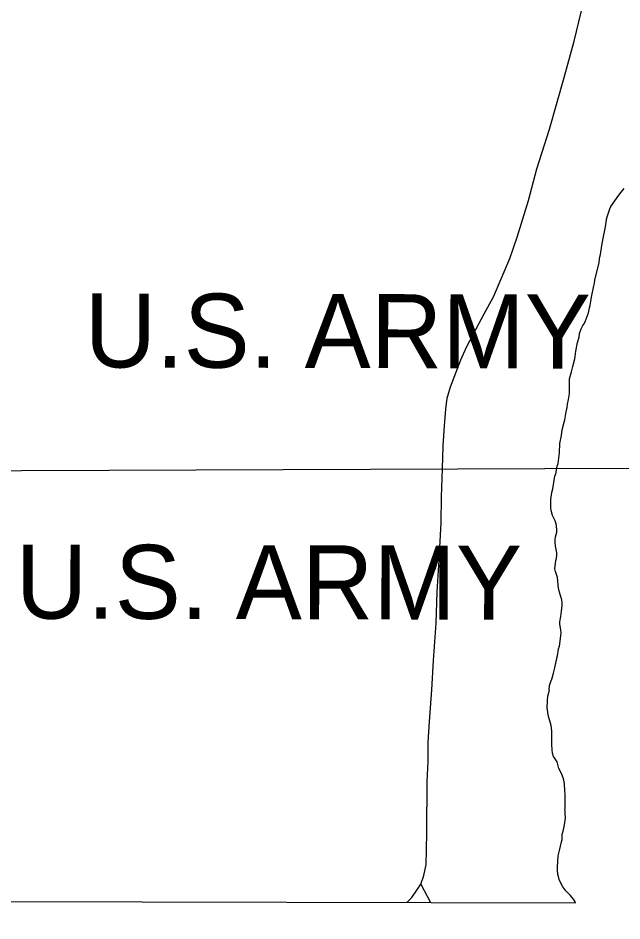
# Model space of a CAD drawing. Extents: x 3172297 to 3210190, y 958463 to 983887.
# Drawn here: x 3187541 to 3188356, y 963866 to 965086 of the extents above; entities that cross this region are included whole.
import ezdxf

# ---------------------------------------------------------------- set-up
doc = ezdxf.new("R2010")
doc.units = 0
for name, color, linetype in [('V-ROAD-CNTR', 7, 'Continuous'), ('V-SITE-VEGE', 7, 'Continuous'), ('V-TOPO-BNDY', 7, 'Continuous'), ('V-TOPO-GNAM-IDEN', 7, 'Continuous'), ('V-TOPO-SHOR', 7, 'Continuous')]:
    doc.layers.add(name, color=color, linetype=linetype)

msp = doc.modelspace()

# ---------------------------------------------------------------- linework, layer by layer
at = {"layer": 'V-ROAD-CNTR'}
for points in [[(3188084.8, 963915.8), (3188089, 963927.4), (3188092.1, 963942.4), (3188092.6, 963962), (3188093.1, 963985.5), (3188093.2, 964054.6), (3188094.6, 964081.6), (3188094.7, 964107.7), (3188096.4, 964135.6), (3188099.8, 964178.2), (3188102.1, 964218.1), (3188105.6, 964268.6), (3188106.8, 964310.6), (3188109.6, 964354), (3188112.2, 964404.2), (3188112.8, 964439.3), (3188114.2, 964477.2), (3188115, 964507.9), (3188116.8, 964535.1), (3188118.6, 964557.8), (3188120.5, 964572.4), (3188124.7, 964587.8), (3188138.9, 964624.3), (3188146.6, 964641.5), (3188155.4, 964658.7), (3188170.5, 964686.3), (3188182.8, 964709.3), (3188193.4, 964733.7), (3188205, 964761.3), (3188215.1, 964790.2), (3188230.4, 964839.8), (3188241.6, 964882.2), (3188258.6, 964936.2), (3188268.1, 964969.5), (3188278.3, 965005.8), (3188291.9, 965054.7), (3188307.7, 965120.7)], [(3188065.9, 963891), (3188072.8, 963898), (3188079.6, 963907.6), (3188084.8, 963915.8)], [(3188084.8, 963915.8), (3188097.9, 963890.9)]]:
    msp.add_lwpolyline(points, dxfattribs=at)
at = {"layer": 'V-SITE-VEGE'}
for p, q in [((3188355.4, 964850.9), (3188359.6, 964855.8)), ((3188341.6, 964831.7), (3188352.1, 964846.7)), ((3188352.1, 964846.7), (3188355.4, 964850.9)), ((3188339.9, 964828.2), (3188341.6, 964831.7)), ((3188336.3, 964817.6), (3188339.9, 964828.2)), ((3188333.9, 964801.7), (3188334.6, 964806.9)), ((3188334.6, 964806.9), (3188335, 964810.8)), ((3188335, 964810.8), (3188336.3, 964817.6)), ((3188331, 964788.6), (3188333.9, 964801.7)), ((3188329.2, 964778.7), (3188331, 964788.6)), ((3188327.6, 964766.5), (3188329.2, 964778.7)), ((3188325.6, 964755.6), (3188326.1, 964760.2)), ((3188326.1, 964760.2), (3188326.6, 964763.4)), ((3188326.6, 964763.4), (3188327.6, 964766.5)), ((3188319.7, 964731.8), (3188325.6, 964755.6)), ((3188315.2, 964709.2), (3188318.3, 964724.2)), ((3188318.3, 964724.2), (3188319.2, 964727.9)), ((3188319.2, 964727.9), (3188319.7, 964731.8)), ((3188313.5, 964697.9), (3188315.2, 964709.2)), ((3188312.8, 964694.6), (3188313.5, 964697.9)), ((3188310.1, 964684.2), (3188311.2, 964687.7)), ((3188311.2, 964687.7), (3188312.8, 964694.6)), ((3188303.5, 964670.7), (3188305.3, 964673.1)), ((3188305.3, 964673.1), (3188307.1, 964677.2)), ((3188307.1, 964677.2), (3188308.4, 964680.7)), ((3188308.4, 964680.7), (3188310.1, 964684.2)), ((3188298.7, 964655.1), (3188299.1, 964660.1)), ((3188299.1, 964660.1), (3188301.3, 964666.4)), ((3188301.3, 964666.4), (3188303.5, 964670.7)), ((3188296.5, 964647.5), (3188298.7, 964655.1)), ((3188293.2, 964628.7), (3188294.2, 964635.9)), ((3188294.2, 964635.9), (3188296.5, 964647.5)), ((3188290.1, 964615.5), (3188292.7, 964625.5)), ((3188292.7, 964625.5), (3188293.2, 964628.7)), ((3188288.5, 964608), (3188290.1, 964615.5)), ((3188285.8, 964598.7), (3188286.5, 964601.8)), ((3188286.5, 964601.8), (3188288.5, 964608)), ((3188285.4, 964591.1), (3188285.8, 964598.7)), ((3188285.6, 964582.6), (3188285.4, 964591.1)), ((3188284.4, 964570.6), (3188285.5, 964578.7)), ((3188285.5, 964578.7), (3188285.6, 964582.6)), ((3188282.4, 964559.7), (3188283.1, 964564.3)), ((3188283.1, 964564.3), (3188284.4, 964570.6)), ((3188279.1, 964543.4), (3188281.1, 964553.9)), ((3188281.1, 964553.9), (3188282.4, 964559.7)), ((3188275.8, 964529.7), (3188278.2, 964540.1)), ((3188278.2, 964540.1), (3188279.1, 964543.4)), ((3188274.6, 964522.1), (3188275.8, 964529.7)), ((3188272.4, 964511.2), (3188274.6, 964522.1)), ((3188272, 964498.8), (3188272.4, 964511.2)), ((3188270.2, 964484.2), (3188272, 964498.8)), ((3188267, 964470.3), (3188269.1, 964480.7)), ((3188269.1, 964480.7), (3188270.2, 964484.2)), ((3188263.1, 964449.8), (3188266, 964467)), ((3188266, 964467), (3188267, 964470.3)), ((3188260.4, 964435.5), (3188261.9, 964445.2)), ((3188261.9, 964445.2), (3188263.1, 964449.8)), ((3188260.2, 964428.3), (3188260.4, 964435.5)), ((3188260.4, 964424.4), (3188260.2, 964428.3)), ((3188261, 964420.7), (3188260.4, 964424.4)), ((3188262.7, 964414.1), (3188261, 964420.7)), ((3188266.1, 964406.9), (3188262.7, 964414.1)), ((3188267.5, 964402.8), (3188266.1, 964406.9)), ((3188268.1, 964399.7), (3188267.5, 964402.8)), ((3188268.5, 964394.7), (3188268.1, 964399.7)), ((3188268.3, 964391.6), (3188268.5, 964394.7)), ((3188266.3, 964381.6), (3188266.5, 964385.3)), ((3188266.3, 964377.9), (3188266.3, 964381.6)), ((3188266.5, 964385.3), (3188267.6, 964388.4)), ((3188267.6, 964388.4), (3188268.3, 964391.6)), ((3188266.9, 964372.7), (3188266.3, 964377.9)), ((3188268.6, 964363.6), (3188266.9, 964372.7)), ((3188267.1, 964353.1), (3188267.9, 964356.1)), ((3188267.9, 964356.1), (3188268.6, 964360.3)), ((3188268.6, 964360.3), (3188268.6, 964363.6)), ((3188265.9, 964341.8), (3188266.6, 964349.4)), ((3188266.6, 964349.4), (3188267.1, 964353.1)), ((3188266.6, 964338.3), (3188265.9, 964341.8)), ((3188269.4, 964330.2), (3188266.6, 964338.3)), ((3188270.8, 964315.4), (3188269.4, 964330.2)), ((3188273.2, 964307.3), (3188270.8, 964315.4)), ((3188275.1, 964300.2), (3188273.2, 964307.3)), ((3188275.8, 964295.6), (3188275.1, 964300.2)), ((3188275.9, 964292.5), (3188275.8, 964295.6)), ((3188273.7, 964277.7), (3188275, 964284.7)), ((3188275, 964284.7), (3188275.9, 964292.5)), ((3188272.6, 964270.3), (3188273.7, 964277.7)), ((3188272.6, 964267.1), (3188272.6, 964270.3)), ((3188274.1, 964259.7), (3188272.6, 964267.1)), ((3188274.3, 964254.9), (3188274.1, 964259.7)), ((3188273.2, 964244.2), (3188274.1, 964251.8)), ((3188274.1, 964251.8), (3188274.3, 964254.9)), ((3188270.1, 964230.7), (3188270.7, 964234)), ((3188270.7, 964234), (3188272, 964237.6)), ((3188272, 964237.6), (3188273.2, 964244.2)), ((3188265.4, 964206.3), (3188269.8, 964227.2)), ((3188269.8, 964227.2), (3188270.1, 964230.7)), ((3188261.8, 964192.8), (3188264.1, 964200.9)), ((3188264.1, 964200.9), (3188265.4, 964206.3)), ((3188258.3, 964178.2), (3188258.6, 964184.3)), ((3188258.6, 964184.3), (3188260.3, 964189.6)), ((3188260.3, 964189.6), (3188261.8, 964192.8)), ((3188256.3, 964169.8), (3188258.5, 964178)), ((3188258.5, 964178), (3188258.3, 964178.2)), ((3188255.6, 964153.9), (3188255.7, 964163.4)), ((3188255.7, 964163.4), (3188256.3, 964169.8)), ((3188257.3, 964142.5), (3188255.6, 964153.9)), ((3188259, 964136.7), (3188257.3, 964142.5)), ((3188260.7, 964130.1), (3188259, 964136.7)), ((3188261.4, 964126), (3188260.7, 964130.1)), ((3188261.6, 964122.9), (3188261.4, 964126)), ((3188261.6, 964113.5), (3188261.6, 964122.9)), ((3188261.8, 964109.4), (3188261.6, 964113.5)), ((3188261.7, 964104.6), (3188261.8, 964109.4)), ((3188262.1, 964097.2), (3188261.7, 964104.6)), ((3188262.6, 964092.9), (3188262.1, 964097.2)), ((3188264.1, 964088.5), (3188262.6, 964092.9)), ((3188266.2, 964085), (3188264.1, 964088.5)), ((3188269, 964080.9), (3188266.2, 964085)), ((3188271.2, 964072.1), (3188269, 964080.9)), ((3188274.7, 964065.4), (3188271.2, 964072.1)), ((3188277.2, 964059.5), (3188274.7, 964065.4)), ((3188278.1, 964056.4), (3188277.2, 964059.5)), ((3188279, 964051.2), (3188278.1, 964056.4)), ((3188279.3, 964041.8), (3188279, 964051.2)), ((3188279.8, 964037.5), (3188279.3, 964041.8)), ((3188279.6, 964035.7), (3188279.8, 964037.5)), ((3188279.9, 964022.4), (3188279.6, 964035.7)), ((3188279.5, 964016.8), (3188279.7, 964017)), ((3188279.9, 964013.8), (3188279.5, 964016.8)), ((3188279.7, 964017), (3188279.9, 964022.4)), ((3188279.9, 964010.2), (3188279.9, 964013.8)), ((3188277.8, 963991.7), (3188279.9, 964001.5)), ((3188280.3, 964006.5), (3188279.9, 964010.2)), ((3188279.9, 964001.5), (3188280.3, 964006.5)), ((3188277.2, 963987.6), (3188277.8, 963991.7)), ((3188275.6, 963976.3), (3188275.9, 963980.2)), ((3188275.9, 963983.5), (3188277.2, 963987.6)), ((3188275.9, 963980.2), (3188275.9, 963983.5)), ((3188272.5, 963963.2), (3188273.4, 963967.2)), ((3188273.4, 963967.2), (3188275, 963972.8)), ((3188275, 963972.8), (3188275.6, 963976.3)), ((3188269.4, 963938.7), (3188270.1, 963954.1)), ((3188270.1, 963954.1), (3188272.5, 963963.2)), ((3188269.4, 963934.7), (3188269.4, 963938.7)), ((3188270, 963929), (3188269.4, 963934.7)), ((3188270.6, 963926), (3188270, 963929)), ((3188271.7, 963922.3), (3188270.6, 963926)), ((3188273.2, 963918.8), (3188271.7, 963922.3)), ((3188276.5, 963912), (3188273.2, 963918.8)), ((3188280.6, 963906.6), (3188276.5, 963912)), ((3188284, 963903.7), (3188280.6, 963906.6)), ((3188286.6, 963900.9), (3188284, 963903.7)), ((3187103.7, 963893.4), (3188293.7, 963890.4)), ((3188291, 963895.7), (3188286.6, 963900.9)), ((3188293.1, 963891.9), (3188291, 963895.7)), ((3188293.7, 963890.4), (3188293.1, 963891.9))]:
    msp.add_line(p, q, dxfattribs=at)
at = {"layer": 'V-TOPO-BNDY'}
msp.add_lwpolyline([(3186048.8, 963896), (3186249.6, 964470), (3198733.3, 964517.6), (3198114.7, 963866.1)], dxfattribs=at)
at = {"layer": 'V-TOPO-SHOR'}
for points in [[(3188266.6, 964349.4), (3188267.1, 964353.1), (3188267.9, 964356.1), (3188268.6, 964360.3), (3188268.6, 964363.6), (3188266.9, 964372.7), (3188266.3, 964377.9), (3188266.3, 964381.6), (3188266.5, 964385.3), (3188267.6, 964388.4), (3188268.3, 964391.6), (3188268.5, 964394.7), (3188268.1, 964399.7), (3188267.5, 964402.8), (3188266.1, 964406.9), (3188262.7, 964414.1), (3188261.9, 964417.2), (3188261, 964420.7), (3188260.4, 964424.4), (3188260.2, 964428.3), (3188260.4, 964435.5), (3188261.9, 964445.2), (3188263.1, 964449.8), (3188266, 964467), (3188267, 964470.3), (3188269.1, 964480.7), (3188270.2, 964484.2), (3188272, 964498.8), (3188272.4, 964511.2), (3188274.6, 964522.1), (3188275.8, 964529.7), (3188278.2, 964540.1), (3188279.1, 964543.4), (3188281.1, 964553.9), (3188282.4, 964559.7), (3188283.1, 964564.3), (3188284.4, 964570.6), (3188285.5, 964578.7), (3188285.6, 964582.6), (3188285.4, 964591.1), (3188285.8, 964598.7), (3188286.5, 964601.8), (3188288.5, 964608), (3188290.1, 964615.5), (3188292.7, 964625.5), (3188293.2, 964628.7), (3188294.2, 964635.9), (3188296.5, 964647.5), (3188298.7, 964655.1), (3188299.1, 964660.1), (3188301.3, 964666.4), (3188303.5, 964670.7), (3188305.3, 964673.1), (3188307.1, 964677.2), (3188308.4, 964680.7), (3188310.1, 964684.2), (3188311.2, 964687.7), (3188312.8, 964694.6), (3188313.5, 964697.9), (3188315.2, 964709.2), (3188318.3, 964724.2), (3188319.2, 964727.9), (3188319.7, 964731.8), (3188325.6, 964755.6), (3188326.1, 964760.2), (3188326.6, 964763.4), (3188327.6, 964766.5), (3188329.2, 964778.7), (3188331, 964788.6), (3188333.9, 964801.7), (3188334.6, 964806.9), (3188335, 964810.8), (3188335.7, 964814.5), (3188336.3, 964817.6), (3188339.9, 964828.2), (3188341.6, 964831.7), (3188352.1, 964846.7), (3188355.4, 964850.9), (3188359.6, 964855.8)], [(3188293.7, 963890.4), (3188293.1, 963891.9), (3188291, 963895.7), (3188286.6, 963900.9), (3188284, 963903.7), (3188280.6, 963906.6), (3188276.5, 963912), (3188273.2, 963918.8), (3188271.7, 963922.3), (3188270.6, 963926), (3188270, 963929), (3188269.4, 963934.7), (3188269.4, 963938.7), (3188270.1, 963954.1), (3188272.5, 963963.2), (3188273.4, 963967.2), (3188275, 963972.8), (3188275.6, 963976.3), (3188275.9, 963980.2), (3188275.9, 963983.5), (3188277.2, 963987.6), (3188277.8, 963991.7), (3188279.9, 964001.5), (3188280.3, 964006.5), (3188279.9, 964010.2), (3188279.9, 964013.8), (3188279.5, 964016.8), (3188279.7, 964017), (3188279.9, 964022.4), (3188279.6, 964035.7), (3188279.8, 964037.5), (3188279.3, 964041.8), (3188279, 964051.2), (3188278.1, 964056.4), (3188277.2, 964059.5), (3188274.7, 964065.4), (3188271.2, 964072.1), (3188269, 964080.9), (3188266.2, 964085), (3188264.1, 964088.5), (3188262.6, 964092.9), (3188262.1, 964097.2), (3188261.7, 964104.6), (3188261.8, 964109.4), (3188261.6, 964113.5), (3188261.6, 964122.9), (3188261.4, 964126), (3188260.7, 964130.1), (3188259, 964136.7), (3188257.3, 964142.5), (3188255.6, 964153.9), (3188255.7, 964163.4), (3188256.3, 964169.8), (3188258.5, 964178), (3188258.3, 964178.2), (3188258.6, 964184.3), (3188260.3, 964189.6), (3188261.8, 964192.8), (3188264.1, 964200.9), (3188265.4, 964206.3), (3188268.9, 964222.6), (3188269.8, 964227.2), (3188270.1, 964230.7), (3188270.7, 964234), (3188272, 964237.6), (3188273.2, 964244.2), (3188274.1, 964251.8), (3188274.3, 964254.9), (3188274.1, 964259.7), (3188272.6, 964267.1), (3188272.6, 964270.3), (3188273.7, 964277.7), (3188275, 964284.7), (3188275.9, 964292.5), (3188275.8, 964295.6), (3188275.1, 964300.2), (3188273.2, 964307.3), (3188270.8, 964315.4), (3188269.4, 964330.2), (3188266.6, 964338.3), (3188265.9, 964341.8), (3188266.6, 964349.4)]]:
    msp.add_lwpolyline(points, dxfattribs=at)

# ---------------------------------------------------------------- texts
at = {"layer": 'V-TOPO-GNAM-IDEN'}
for p in [(3187630.7, 964614.1), (3187537.6, 964274.7)]:
    msp.add_text('U.S. ARMY', height=100, rotation=359.8583, dxfattribs=at).set_placement(p)

doc.saveas('drawing.dxf')
